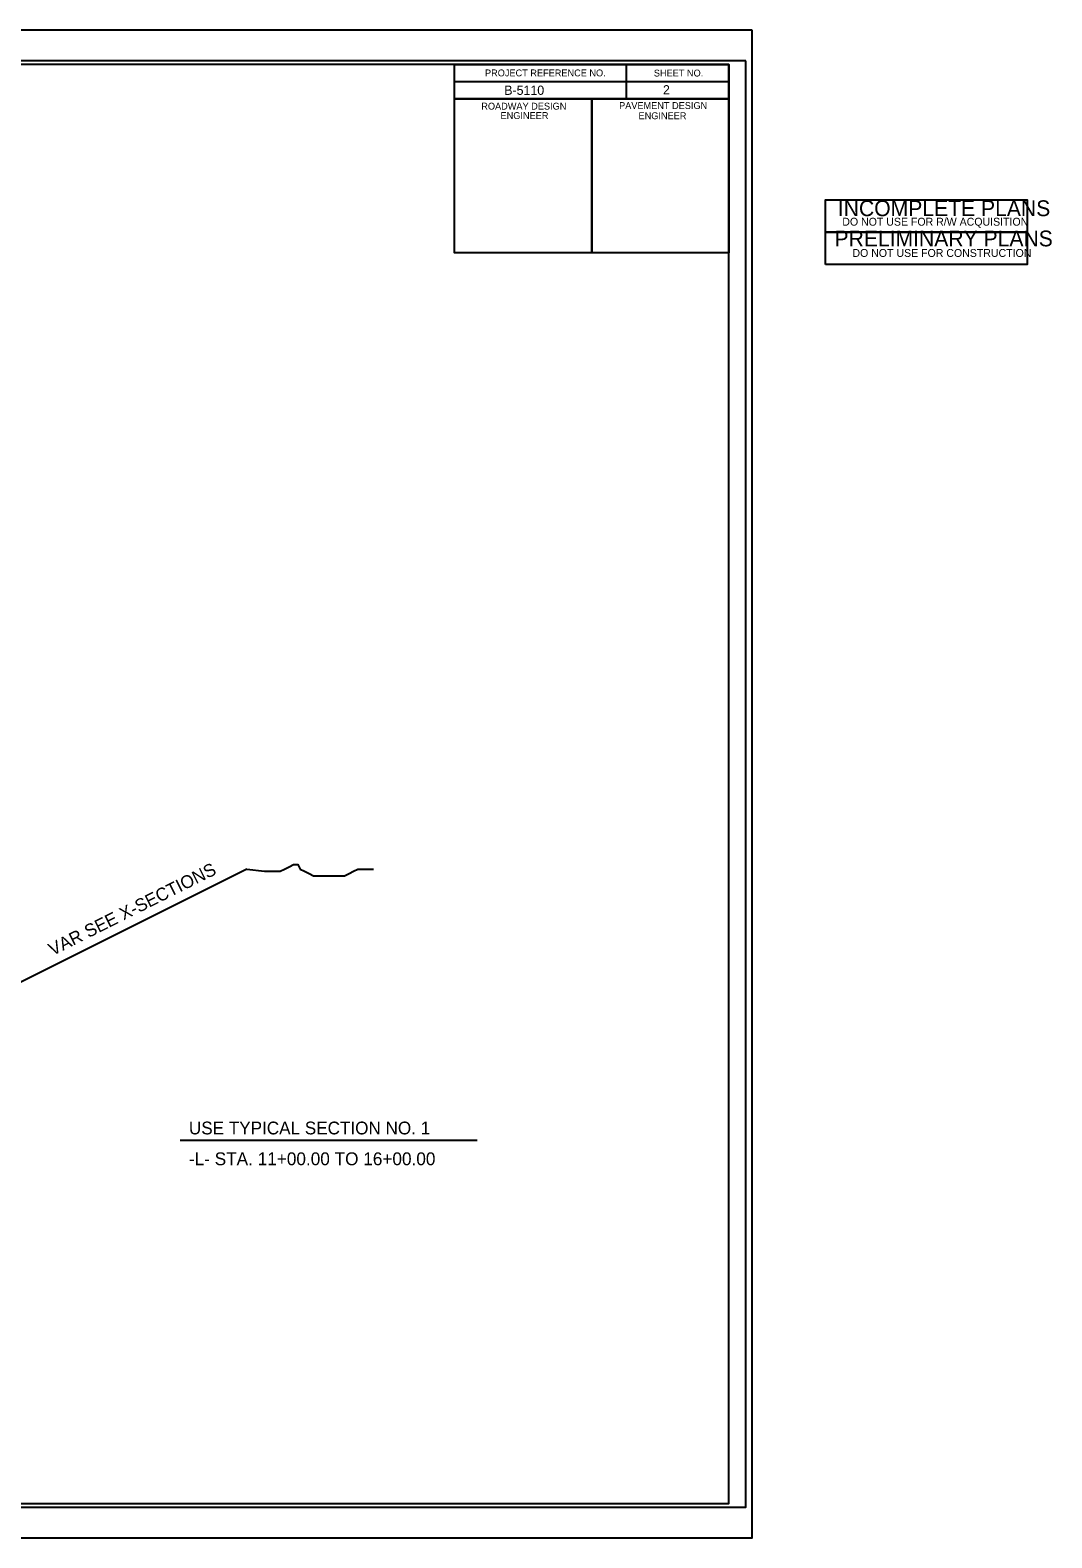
# Model space of a CAD drawing. Extents: x 573793 to 573946, y -53322 to -53234.
# Drawn here: x 573886 to 573945.6, y -53321.6 to -53233.6 of the extents above; entities that cross this region are included whole.
import ezdxf

# ---------------------------------------------------------------- set-up
doc = ezdxf.new("R2010")
doc.units = 0
for name, color, linetype in [('Sheet Cutting Line CELL', 7, 'Continuous'), ('Sheet Data Field CELL', 7, 'Continuous'), ('Sheet Plot Border Inside CELL', 7, 'Continuous'), ('Sheet Plot Border Outside CELL', 7, 'Continuous'), ('Sheet Sticker Incomplete CELL', 7, 'Continuous'), ('Sheet Sticker Preliminary CELL', 7, 'Continuous'), ('Sheet Typical CELL', 7, 'Continuous'), ('Typical Slope Point Local CELL', 7, 'Continuous'), ('Typical Text Label CELL', 7, 'Continuous')]:
    doc.layers.add(name, color=color, linetype=linetype)

msp = doc.modelspace()

# ---------------------------------------------------------------- linework, layer by layer
at = {"layer": 'Sheet Cutting Line CELL'}
for p, q in [((573928.086, -53233.554), (573793.366, -53233.554)), ((573793.366, -53321.554), (573928.086, -53321.554))]:
    msp.add_line(p, q, dxfattribs=at)
at = {"layer": 'Sheet Plot Border Inside CELL'}
msp.add_lwpolyline([(573927.726, -53235.35), (573794.406, -53235.35), (573794.406, -53319.758), (573927.726, -53319.758)], close=True, dxfattribs=at)
at = {"layer": 'Sheet Plot Border Outside CELL'}
msp.add_lwpolyline([(573928.086, -53233.554), (573793.366, -53233.554), (573793.366, -53321.554), (573928.086, -53321.554)], close=True, dxfattribs=at)
at = {"layer": 'Sheet Sticker Incomplete CELL'}
msp.add_lwpolyline([(573932.37, -53245.345), (573932.37, -53243.465), (573944.13, -53243.465), (573944.13, -53245.345)], close=True, dxfattribs=at)
at = {"layer": 'Sheet Sticker Preliminary CELL'}
msp.add_lwpolyline([(573932.37, -53247.225), (573932.37, -53245.345), (573944.13, -53245.345), (573944.13, -53247.225)], close=True, dxfattribs=at)
at = {"layer": 'Sheet Typical CELL'}
for p, q in [((573920.726, -53235.558), (573920.726, -53237.558)), ((573910.722, -53236.558), (573926.726, -53236.558)), ((573918.726, -53237.558), (573918.726, -53246.554))]:
    msp.add_line(p, q, dxfattribs=at)
for points in [[(573926.726, -53235.554), (573806.726, -53235.554), (573806.726, -53319.554), (573926.726, -53319.554)], [(573910.722, -53235.554), (573926.726, -53235.554), (573926.726, -53237.558), (573910.722, -53237.558)], [(573910.722, -53237.558), (573918.726, -53237.558), (573918.726, -53246.558), (573910.722, -53246.558)], [(573918.726, -53237.558), (573926.726, -53237.558), (573926.726, -53246.558), (573918.726, -53246.558)]]:
    msp.add_lwpolyline(points, close=True, dxfattribs=at)
at = {"layer": 'Typical Slope Point Local CELL'}
msp.add_line((573898.6, -53282.52), (573884.983, -53289.328), dxfattribs=at)
msp.add_lwpolyline([(573898.6, -53282.52), (573899.637, -53282.649), (573899.896, -53282.649), (573900.286, -53282.649), (573900.545, -53282.649), (573900.805, -53282.52), (573901.064, -53282.39), (573901.323, -53282.26), (573901.583, -53282.26), (573901.713, -53282.52), (573901.972, -53282.649), (573902.231, -53282.779), (573902.491, -53282.909), (573902.75, -53282.909), (573903.009, -53282.909), (573903.269, -53282.909), (573903.528, -53282.909), (573903.787, -53282.909), (573904.047, -53282.909), (573904.306, -53282.909), (573904.565, -53282.779), (573904.825, -53282.649), (573905.084, -53282.52), (573905.474, -53282.52), (573905.733, -53282.52), (573905.992, -53282.52)], dxfattribs=at)
at = {"layer": 'Typical Text Label CELL'}
msp.add_line((573894.71, -53298.343), (573912.034, -53298.343), dxfattribs=at)

# ---------------------------------------------------------------- texts
at = {"layer": 'Sheet Data Field CELL'}
for s, p in [('B-5110   ', (573913.622, -53237.33)), ('2  ', (573922.883, -53237.306))]:
    msp.add_text(s, height=0.54, dxfattribs=at).set_placement(p)
at = {"layer": 'Sheet Sticker Incomplete CELL'}
for s, height, p in [('INCOMPLETE PLANS', 0.9216, (573933.086, -53244.409)), ('DO NOT USE FOR R/W ACQUISITION', 0.4608, (573933.346, -53244.965))]:
    msp.add_text(s, height=height, dxfattribs=at).set_placement(p)
at = {"layer": 'Sheet Sticker Preliminary CELL'}
for s, height, p in [('PRELIMINARY PLANS', 0.9216, (573932.89, -53246.173)), ('DO NOT USE FOR CONSTRUCTION', 0.4608, (573933.938, -53246.789)), ('DO NOT USE FOR CONSTRUCTION', 0.4608, (573933.938, -53246.789))]:
    msp.add_text(s, height=height, dxfattribs=at).set_placement(p)
at = {"layer": 'Sheet Typical CELL'}
for s, height, p in [('PROJECT REFERENCE NO.', 0.40001, (573912.498, -53236.25)), ('SHEET NO.', 0.4, (573922.35, -53236.258)), ('ROADWAY DESIGN', 0.40001, (573912.282, -53238.19)), ('PAVEMENT DESIGN', 0.40001, (573920.322, -53238.154)), ('ENGINEER', 0.4, (573913.406, -53238.738)), ('ENGINEER', 0.4, (573921.458, -53238.75))]:
    msp.add_text(s, height=height, dxfattribs=at).set_placement(p)
at = {"layer": 'Typical Slope Point Local CELL'}
msp.add_text('VAR SEE X-SECTIONS', height=0.75, rotation=26.56505, dxfattribs=at).set_placement((573887.267, -53287.599))
at = {"layer": 'Typical Text Label CELL'}
for s, height, p in [('USE TYPICAL SECTION NO. 1', 0.74597, (573895.222, -53298.005)), ('-L- STA. 11+00.00 TO 16+00.00', 0.75, (573895.222, -53299.804))]:
    msp.add_text(s, height=height, dxfattribs=at).set_placement(p)

doc.saveas('drawing.dxf')
